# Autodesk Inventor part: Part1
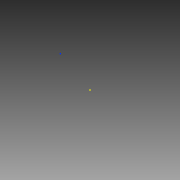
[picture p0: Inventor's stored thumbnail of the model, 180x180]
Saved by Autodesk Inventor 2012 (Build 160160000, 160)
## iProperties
Created: 2018-05
Part Number: Part1
Material: Default
Document SubType Name: Modeling
Designer: Elkawokgy
Density: 1 g/cm^3
Author: Elkawokgy
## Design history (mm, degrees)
sketch "Sketch1"
  geometry: C1 r 3.95 at (0, 0); 1 further point
  constraints: 1 centre point, 1 coincident
  dimensions: "d0" = 7.9 dimension on point (0, 0) C1.centre C1; "d0" = 7.9 diameter of C1
extrude "Extrusion1" new body sketch "Sketch1" stored distance "d1" = 5; taper "d2" = 0 deg
body "Solid1"
